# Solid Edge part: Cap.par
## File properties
Author: Deepak Maini
Template: Normal.par
Last saved by: Administrator
Revision: 5
Application: Solid Edge
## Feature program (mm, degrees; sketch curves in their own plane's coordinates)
sketch for "unnamed Protrusion 1" plane through (0, 0, 0) normal (0, -1, 0) x-axis (1, 0, 0)
  line (-54, 0) -> (-54, 12)
  line (-54, 12) -> (-31.749, 12)
  arc centre (0, -24) radius 48 from (-31.749, 12) to (31.749, 12) cw
  line (31.749, 12) -> (54, 12)
  line (54, 12) -> (54, 0)
  line (54, 0) -> (27.6274, 0)
  line (27.6274, -16) -> (27.6274, 0)
  line (22.6274, -16) -> (27.6274, -16)
  arc centre (0, -24) radius 24 from (-22.6274, -16) to (22.6274, -16) cw
  line (-27.6274, -16) -> (-22.6274, -16)
  line (-27.6274, 0) -> (-27.6274, -16)
  line (-27.6274, 0) -> (-54, 0)
  dimension (linear) = 54
extrude "unnamed Protrusion 1" add finite 46 symmetric
sketch for "unnamed Hole 1" plane through (42.8745, 0, 12) normal (0, 0, 1) x-axis (0, 1, 0)
hole "unnamed Hole 1" through
sketch for "unnamed Cutout 1" plane through (42.8745, 0, 12) normal (0, 0, 1) x-axis (0, 1, 0)
extrude "unnamed Cutout 1" cut through along +normal
sketch for "unnamed Cutout 2" plane through (38, 0, 12) normal (0, 0, 1) x-axis (0, 1, 0)
  line (-23, -16) -> (-23, -10.8569)
  arc centre (0, 38) radius 54 from (23, -10.8569) to (-23, -10.8569) cw
  line (23, -16) -> (23, -10.8569)
  line (1.0714, -23.7143) -> (23, -16)
  line (-23, -16) -> (1.0714, -23.7143)
extrude "unnamed Cutout 2" cut through along -normal
mirror "unnamed Mirror 1" of "unnamed Cutout 2", "unnamed Cutout 1", "unnamed Hole 1" about plane through (0, 0, 0) normal (1, 0, 0)
hole "unnamed Hole 2" through
extrude "unnamed Cutout 3" cut through
extrude "unnamed Cutout 4" cut through
sketch for "unnamed Hole 3" plane through (25.1274, 0, 24) normal (0, 0, -1) x-axis (0, 1, 0)
  hole centre (0, -25.1274) bore radius 3
hole "unnamed Hole 3" through
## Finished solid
Body 1: solid body, 21 faces, 50 edges, 28 vertices.
  Faces by surface: plane 11, cylinder 10
  Edges by curve: line 30, circle 16, intersection 4
Bounding box of the edges (mm): 108.000 x 46.000 x 40.000, from (-54, -23, -16) to (54, 23, 24).
Cylindrical faces by radius (mm): R3 x1, R4 x1, R6 x2, R17 x2, R24 x1, R48 x1, R54 x2
Planar faces by outward normal: +x 1, +y 1, +z 3, -x 1, -y 1, -z 4
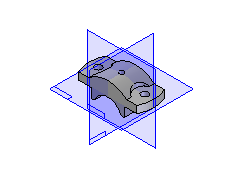
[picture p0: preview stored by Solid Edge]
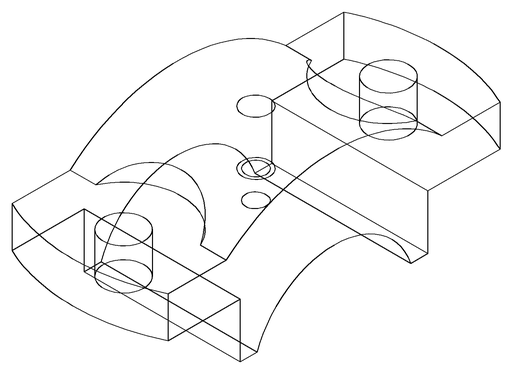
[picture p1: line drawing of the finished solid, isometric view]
